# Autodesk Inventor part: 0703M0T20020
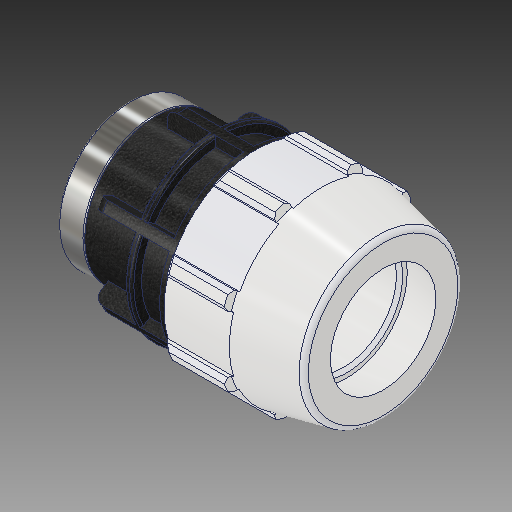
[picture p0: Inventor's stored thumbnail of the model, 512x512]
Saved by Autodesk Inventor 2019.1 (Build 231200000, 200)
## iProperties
Created: 2017-02
Part Number: 0703M0T20020
Material: PVC-Piping
Description: PLASSON FEMALE ADAPTOR G 2'' - 2''F
Document SubType Name: Modeling
Designer: KIM
Mass: 92.6774 g
Surface Area: 199.44 cm^2
Volume: 66.1981 cm^3
Density: 1.4 g/cm^3
Appearance: PTFE
Author: KIM
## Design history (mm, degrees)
derived "0703M0T.ipt"
feature "Solid1::0703M0T.ipt"
tag "TaggingFeature1"
body "Solid1"
other parameters: "d2" = 60.1, "d4" = 20.71914, "d5" = 36.2585, "d7" = 113.03, "d9" = 20.71914, "d11" = 4.14383, "d12" = 90.424, "d13" = 120 deg, "d14" = 90.15, "d15" = 12 deg, "d16" = 101.727, "d18" = 3.005, "d19" = 35 deg, "d20" = 17.5 deg, "d21" = 105.1179, "d23" = 0, "d25" = 360 deg, "d27" = 2.2606, "d34" = 5.6515, "d35" = 43.5102, "d36" = 0, "d42" = 36.2585, "d43" = 3.3909, "d46" = 1.803, "d49" = 119.126, "d51" = 145.034, "d53" = 1.202, "d55" = 360 deg, "d61" = 29.972, "d62" = 57.095, "d63" = 56.656, "d64" = 48.34467, "d65" = 5.6515, "d66" = 0.5, "d67" = 1, "d68" = 14.986, "d69" = 81.3816, "d70" = 1.27, "d_" = 60.1, "E_" = 113.03, "H_" = 145.034, "l_" = 119.126, "l_2" = 29.972, "G_" = 56.656
